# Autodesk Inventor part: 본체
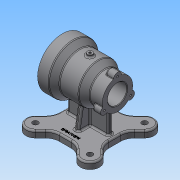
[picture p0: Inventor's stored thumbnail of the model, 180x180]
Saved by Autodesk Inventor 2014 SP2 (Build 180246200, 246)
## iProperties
Created: 2017-03
Part Number: 본체
Material: Generic
Document SubType Name: Modeling
Designer: 702
Density: 1 g/cm^3
Appearance: Default
Author: 702
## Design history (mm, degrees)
sketch "스케치1"
  geometry: L1 (-50, 0)-(50, 0); L2 (-50, 0)-(-50, 45); L3 (-50, 45)-(-30, 45); L4 (-30, 45)-(-19, 36); L5 (-19, 36)-(15, 36); L6 (15, 36)-(27, 27.5); L7 (27, 27.5)-(50, 27.5); L8 (50, 27.5)-(50, 0); 2 further points
  constraints: 16 end point, 3 parallel, 2 perpendicular, 1 coincident, 1 horizontal, 1 midpoint
  dimensions: "d0" = 100 distance of L1.start L1.end; "d1" = 20 distance of L2.end L3.end; "d3" = 90 diameter of L3 L1; "d4" = 72 diameter of L5 L1; "d5" = 55 diameter of L7 L1; "d6" = 31 horizontal distance of L2.end L4.end; "d7" = 65 horizontal distance of L2.end L5.end; "d8" = 23 distance of L7.end L6.end
revolve "회전1" sketch "스케치1" stored, may be unused: angle "d9" = 90 deg
sketch "스케치2"
  geometry: C1 r 45 at (0, 0) reference
hole "구멍1" sketch "스케치2" at (0, 0) diameter "d10" = 52; stored, may be unused: countersink angle "d14" = 90 deg, drill point angle "d16" = 0 deg; dims "d11" = 6, "d12" = 70, "d13" = 23, "d15" = 70
sketch "스케치3"
  geometry: C1 r 26 at (0, 0) reference
hole "구멍2" sketch "스케치3" at (0, 0) diameter "d17" = 35; stored, may be unused: countersink angle "d21" = 90 deg, drill point angle "d23" = 118 deg; dims "d18" = 6, "d19" = 70, "d20" = 23, "d22" = 70
node "작업 평면1"
sketch "스케치4"
  geometry: L1 (45, 45)-(-45, 45); L2 (-45, 45)-(-45, -45); L3 (-45, -45)-(20.958, -45); L4 (45, -20.958)-(45, 45); L5 (45, 45)-(-45, -45); L6 (-45, 45)-(49.497, -49.497); L7 (45, 0)-(-45, 0); L8 (61.518, -37.477)-(37.477, -61.518); L9 (37.477, -61.518)-(20.958, -45); L10 (61.518, -37.477)-(45, -20.958); A1 r 70 centre (0, 0) between (49.497, -49.497) and (59.97, -36.106); A2 r 17 centre (49.497, -49.497) between (36.106, -59.97) and (59.97, -36.106); 3 further points
  constraints: 20 end point, 7 point on circle, 5 midpoint, 4 perpendicular, 3 coincident, 3 parallel, 3 tangent, 2 centre point, 2 point on line, 1 horizontal
  dimensions: "d26" = 90 distance of L2.end L1.end; "d27" = 140 diameter of A1; "d28" = 90 distance between parallel lines of L2 L4; "d30" = 45 deg angle of L7 L6; "d103" = 34 diameter of A2
extrude "돌출1" join sketch "스케치4" distance "d31" = 12; taper "d32" = 0 deg
fillet "모깎기1" dims "d36" = 25
sketch "스케치5"
  geometry: L1 (-37, -4)-(37, -4); L2 (37, -4)-(37, 4); L3 (37, 4)-(-37, 4); L4 (-37, 4)-(-37, -4); L5 (-37, -4)-(37, 4); L6 (37, -4)-(-37, 4); 1 further point
  constraints: 12 end point, 2 midpoint, 2 parallel, 1 horizontal, 1 perpendicular
  dimensions: "d37" = 74 distance of L3.end L2.end; "d38" = 8 distance of L2.end L1.end
extrude "돌출2" join sketch "스케치5" stored distance "d39" = 12; taper "d40" = 0 deg
sketch "스케치6"
  geometry: L1 (-70, 25)-(-31.096, 18.14); L2 (-70, 37.477)-(-70, 66.497) reference; L3 (-70, 28.281)-(-70, 37.477) reference; A1 r 36 centre (0, 0) between (-35.777, -4) and (-35.777, 4) reference; 2 further points
  constraints: 2 end point, 1 point on circle, 1 point on line
  dimensions: "d41" = 25 vertical distance of point (0, 0) L1.start; "d104" = 100 deg angle of L2 L1
feature "리브1" sketch "스케치6" dims "d43" = 1, "d44" = 8, "d45" = 0, "d46" = 0, "d47" = 1, "d48" = 1
sketch "스케치7"
  geometry: C1 r 7 at (0, 27.5); 2 further points
  constraints: 2 vertical alignment, 1 centre point, 1 other
  dimensions: "d49" = 14 diameter of C1
extrude "돌출3" join sketch "스케치7" distance "d50" = 15; taper "d51" = 0 deg
sketch "스케치8"
  geometry: A1 r 7 centre (0, 0) between (6.943, -0.891) and (-6.943, -0.891) reference; A2 r 7 centre (-23.816, -41.25) between (-26.516, -34.792) and (-19.573, -46.817) reference; A3 r 7 centre (23.816, -41.25) between (19.573, -46.817) and (26.516, -34.792) reference
hole "구멍3" sketch "스케치8" at (0, 0), (-23.816, -41.25), (23.816, -41.25) diameter "d55" = 3.242; stored, may be unused: countersink angle "d59" = 90 deg, drill point angle "d61" = 118 deg; dims "d56" = 9, "d57" = 70, "d58" = 23, "d60" = 11
sketch "스케치9"
  geometry: 2 further points
  constraints: 1 vertical alignment
  dimensions: "d62" = 40 distance of point (0, 0) point (0, 40)
hole "구멍4" sketch "스케치9" at (0, 40) diameter "d63" = 3.242; stored, may be unused: countersink angle "d67" = 90 deg, drill point angle "d69" = 118 deg; dims "d64" = 9, "d65" = 70, "d66" = 23, "d68" = 11
node "작업 평면2"
sketch "스케치10"
  geometry: C1 r 5 at (0, 0); 1 further point
  constraints: 1 centre point, 1 coincident
  dimensions: "d74" = 10 diameter of C1
extrude "돌출4" join sketch "스케치10" stored distance "d75" = 10; taper "d76" = 0 deg
sketch "스케치11"
  geometry: C1 r 5 at (0, 0) reference
hole "구멍5" sketch "스케치11" at (0, 0) diameter "d77" = 4.134; stored, may be unused: countersink angle "d81" = 90 deg, drill point angle "d83" = 118 deg; dims "d78" = 9, "d79" = 70, "d80" = 23, "d82" = 11
sketch "스케치12"
  geometry: L1 (45, -10.603)-(45, 10.603) reference; 5 further points
  constraints: 1 other
  dimensions: "d84" = 35 distance of point (0, -35) point (0, 0); "d85" = 45 distance from line of L1 point (0, -35)
feature "엠보싱1" sketch "스케치12" dims "d86" = 0.5, "d87" = 0
chamfer "모따기1" distance "d88" = 1; stored, may be unused: second distance "d89" = 2, angle "d90" = 45 deg
fillet "모깎기2" dims "d91" = 3
fillet "모깎기3" dims "d92" = 3
fillet "모깎기4" dims "d93" = 1
fillet "모깎기5" dims "d94" = 3
fillet "모깎기6" dims "d95" = 3
sketch "스케치14"
  geometry: A1 r 14 centre (49.497, 49.497) between (59.397, 39.598) and (39.598, 59.397) reference; A2 r 14 centre (-49.497, 49.497) between (-39.598, 59.397) and (-59.397, 39.598) reference; A3 r 14 centre (-49.497, -49.497) between (-59.397, -39.598) and (-39.598, -59.397) reference; A4 r 14 centre (49.497, -49.497) between (39.598, -59.397) and (59.397, -39.598) reference; 1 further point
hole "구멍7" sketch "스케치14" at (-49.497, -49.497), (49.497, -49.497), (49.497, 49.497), (-49.497, 49.497) diameter "d105" = 10; stored, may be unused: countersink angle "d109" = 90 deg, drill point angle "d111" = 118 deg; dims "d106" = 6, "d107" = 4, "d108" = 2, "d110" = 8
node "솔리드1"
pattern_circular "원형 패턴1" dims angle "d34" = 360 deg
mirror "대칭1"
pattern_circular "원형 패턴2" dims angle "d53" = 360 deg
pattern_circular "원형 패턴3" dims angle "d71" = 360 deg
other parameters: "d24" = -82
